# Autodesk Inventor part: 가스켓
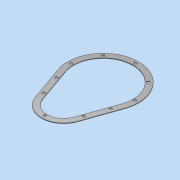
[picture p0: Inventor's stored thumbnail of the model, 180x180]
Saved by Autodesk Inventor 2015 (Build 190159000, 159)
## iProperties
Created: 2024-05
Part Number: 가스켓
Material: 일반
Document SubType Name: Modeling
Designer: Administrator
Density: 1 g/cm^3
Appearance: 기본값
Author: Administrator
Author: jhkim
Creation Date: 2024-05-07
Sending System: Autodesk Inventor 2025
Preprocessor: ST-DEVELOPER v20
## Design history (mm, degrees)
node "가스켓1"
node "솔리드1"
node "기준1"
